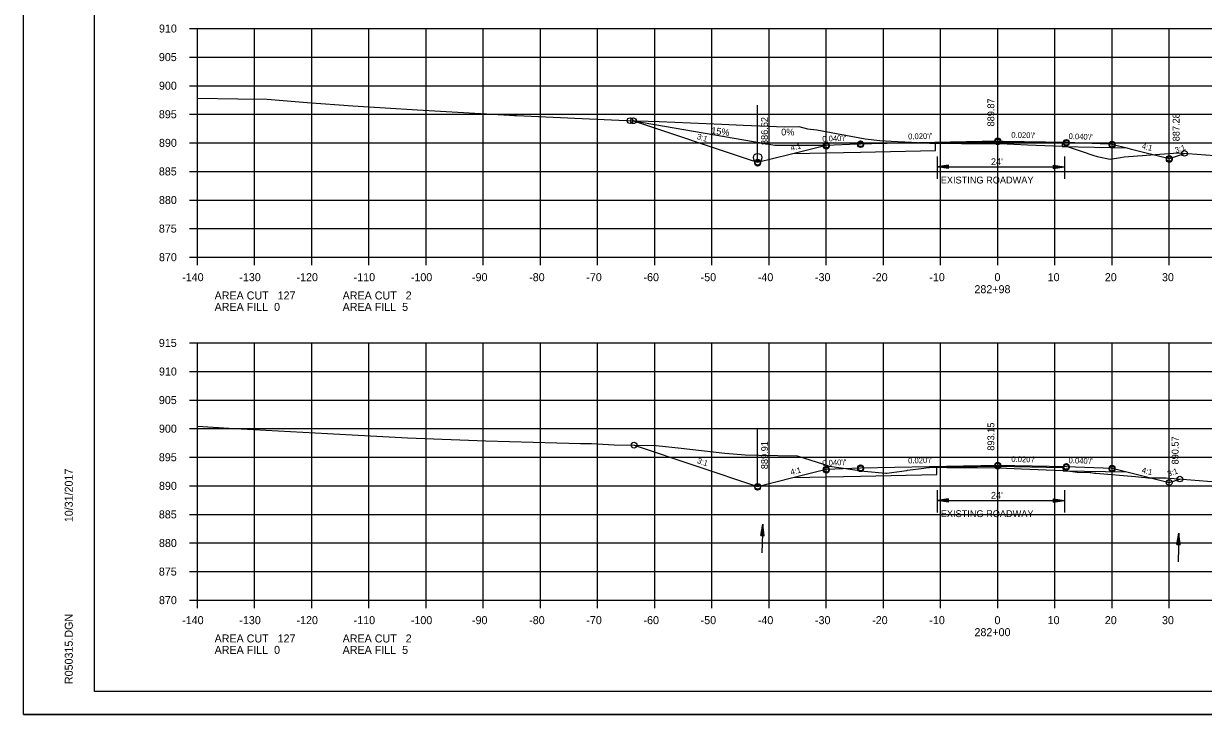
# Model space of a CAD drawing. Extents: x 1486524 to 1499135, y 326561 to 337924.
# Drawn here: x 1488812.5 to 1489018.9, y 331926 to 332046.8 of the extents above; entities that cross this region are included whole.
import ezdxf

# ---------------------------------------------------------------- set-up
doc = ezdxf.new("R2010")
doc.units = 0
for name, color, linetype in [('E_Const Align', 7, 'Continuous'), ('E_Const Align Station', 7, 'Continuous'), ('E_Ownership Information', 7, 'Continuous'), ('E_Property Line', 7, 'Continuous'), ('E_Proposed ROW and Easements', 7, 'Continuous'), ('E_Proposed ROW Fig Annot', 7, 'Continuous'), ('E_Quarter Calls', 7, 'Continuous'), ('E_Station Offset', 7, 'Continuous'), ('E_Survey Point', 7, 'Continuous'), ('E_Title Sheet', 7, 'Continuous'), ('E_Tract Number', 7, 'Continuous'), ('R_Water Annot', 7, 'Continuous'), ('R_Xsect Elev', 7, 'Continuous'), ('R_Xsect Slope', 7, 'Continuous')]:
    doc.layers.add(name, color=color, linetype=linetype)

msp = doc.modelspace()

# ---------------------------------------------------------------- linework, layer by layer
at = {"layer": 'E_Const Align'}
for p, q in [((1488841.49, 332045.94), (1488842.89, 332045.94)), ((1488842.89, 332005.94), (1488842.89, 332045.94)), ((1488841.49, 332040.94), (1488842.89, 332040.94)), ((1488841.49, 332035.94), (1488842.89, 332035.94)), ((1488841.49, 332030.94), (1488842.89, 332030.94)), ((1488841.49, 332025.94), (1488842.89, 332025.94)), ((1488841.49, 332020.94), (1488842.89, 332020.94)), ((1488841.49, 332015.94), (1488842.89, 332015.94)), ((1488841.49, 332010.94), (1488842.89, 332010.94)), ((1488841.49, 332005.94), (1488842.89, 332005.94)), ((1488842.89, 332005.94), (1489122.89, 332005.94)), ((1488842.89, 332004.54), (1488842.89, 332005.94)), ((1488852.89, 332004.54), (1488852.89, 332005.94)), ((1488862.89, 332004.54), (1488862.89, 332005.94)), ((1488872.89, 332004.54), (1488872.89, 332005.94)), ((1488882.89, 332004.54), (1488882.89, 332005.94)), ((1488892.89, 332004.54), (1488892.89, 332005.94)), ((1488902.89, 332004.54), (1488902.89, 332005.94)), ((1488912.89, 332004.54), (1488912.89, 332005.94)), ((1488922.89, 332004.54), (1488922.89, 332005.94)), ((1488932.89, 332004.54), (1488932.89, 332005.94)), ((1488942.89, 332004.54), (1488942.89, 332005.94)), ((1488952.89, 332004.54), (1488952.89, 332005.94)), ((1488962.89, 332004.54), (1488962.89, 332005.94)), ((1488972.89, 332004.54), (1488972.89, 332005.94)), ((1488982.89, 332004.54), (1488982.89, 332005.94)), ((1488992.89, 332004.54), (1488992.89, 332005.94)), ((1489002.89, 332004.54), (1489002.89, 332005.94)), ((1489012.89, 332004.54), (1489012.89, 332005.94)), ((1488841.49, 331990.94), (1488842.89, 331990.94)), ((1488842.89, 331945.94), (1488842.89, 331990.94)), ((1488841.49, 331985.94), (1488842.89, 331985.94)), ((1488841.49, 331980.94), (1488842.89, 331980.94)), ((1488841.49, 331975.94), (1488842.89, 331975.94)), ((1488841.49, 331970.94), (1488842.89, 331970.94)), ((1488841.49, 331965.94), (1488842.89, 331965.94)), ((1488841.49, 331960.94), (1488842.89, 331960.94)), ((1488841.49, 331955.94), (1488842.89, 331955.94)), ((1488841.49, 331950.94), (1488842.89, 331950.94)), ((1488841.49, 331945.94), (1488842.89, 331945.94)), ((1488842.89, 331945.94), (1489122.89, 331945.94)), ((1488842.89, 331944.54), (1488842.89, 331945.94)), ((1488852.89, 331944.54), (1488852.89, 331945.94)), ((1488862.89, 331944.54), (1488862.89, 331945.94)), ((1488872.89, 331944.54), (1488872.89, 331945.94)), ((1488882.89, 331944.54), (1488882.89, 331945.94)), ((1488892.89, 331944.54), (1488892.89, 331945.94)), ((1488902.89, 331944.54), (1488902.89, 331945.94)), ((1488912.89, 331944.54), (1488912.89, 331945.94)), ((1488922.89, 331944.54), (1488922.89, 331945.94)), ((1488932.89, 331944.54), (1488932.89, 331945.94)), ((1488942.89, 331944.54), (1488942.89, 331945.94)), ((1488952.89, 331944.54), (1488952.89, 331945.94)), ((1488962.89, 331944.54), (1488962.89, 331945.94)), ((1488972.89, 331944.54), (1488972.89, 331945.94)), ((1488982.89, 331944.54), (1488982.89, 331945.94)), ((1488992.89, 331944.54), (1488992.89, 331945.94)), ((1489002.89, 331944.54), (1489002.89, 331945.94)), ((1489012.89, 331944.54), (1489012.89, 331945.94))]:
    msp.add_line(p, q, dxfattribs=at)
at = {"layer": 'E_Ownership Information'}
for p, q in [((1488842.89, 332045.94), (1489122.89, 332045.94)), ((1488842.89, 332005.94), (1488842.89, 332045.94)), ((1488852.89, 332005.94), (1488852.89, 332045.94)), ((1488862.89, 332005.94), (1488862.89, 332045.94)), ((1488872.89, 332005.94), (1488872.89, 332045.94)), ((1488882.89, 332005.94), (1488882.89, 332045.94)), ((1488892.89, 332005.94), (1488892.89, 332045.94)), ((1488902.89, 332005.94), (1488902.89, 332045.94)), ((1488912.89, 332005.94), (1488912.89, 332045.94)), ((1488922.89, 332005.94), (1488922.89, 332045.94)), ((1488932.89, 332005.94), (1488932.89, 332045.94)), ((1488942.89, 332005.94), (1488942.89, 332045.94)), ((1488952.89, 332005.94), (1488952.89, 332045.94)), ((1488962.89, 332005.94), (1488962.89, 332045.94)), ((1488972.89, 332005.94), (1488972.89, 332045.94)), ((1488982.89, 332005.94), (1488982.89, 332045.94)), ((1488992.89, 332005.94), (1488992.89, 332045.94)), ((1489002.89, 332005.94), (1489002.89, 332045.94)), ((1489012.89, 332005.94), (1489012.89, 332045.94)), ((1488842.89, 332040.94), (1489122.89, 332040.94)), ((1488842.89, 332035.94), (1489122.89, 332035.94)), ((1488842.89, 332030.94), (1489122.89, 332030.94)), ((1488842.89, 332025.94), (1489122.89, 332025.94)), ((1488842.89, 332020.94), (1489122.89, 332020.94)), ((1488842.89, 332015.94), (1489122.89, 332015.94)), ((1488842.89, 332010.94), (1489122.89, 332010.94)), ((1488842.89, 332005.94), (1489122.89, 332005.94)), ((1488842.89, 331990.94), (1489122.89, 331990.94)), ((1488842.89, 331945.94), (1488842.89, 331990.94)), ((1488852.89, 331945.94), (1488852.89, 331990.94)), ((1488862.89, 331945.94), (1488862.89, 331990.94)), ((1488872.89, 331945.94), (1488872.89, 331990.94)), ((1488882.89, 331945.94), (1488882.89, 331990.94)), ((1488892.89, 331945.94), (1488892.89, 331990.94)), ((1488902.89, 331945.94), (1488902.89, 331990.94)), ((1488912.89, 331945.94), (1488912.89, 331990.94)), ((1488922.89, 331945.94), (1488922.89, 331990.94)), ((1488932.89, 331945.94), (1488932.89, 331990.94)), ((1488942.89, 331945.94), (1488942.89, 331990.94)), ((1488952.89, 331945.94), (1488952.89, 331990.94)), ((1488962.89, 331945.94), (1488962.89, 331990.94)), ((1488972.89, 331945.94), (1488972.89, 331990.94)), ((1488982.89, 331945.94), (1488982.89, 331990.94)), ((1488992.89, 331945.94), (1488992.89, 331990.94)), ((1489002.89, 331945.94), (1489002.89, 331990.94)), ((1489012.89, 331945.94), (1489012.89, 331990.94)), ((1488842.89, 331985.94), (1489122.89, 331985.94)), ((1488842.89, 331980.94), (1489122.89, 331980.94)), ((1488842.89, 331975.94), (1489122.89, 331975.94)), ((1488842.89, 331970.94), (1489122.89, 331970.94)), ((1488842.89, 331965.94), (1489122.89, 331965.94)), ((1488842.89, 331960.94), (1489122.89, 331960.94)), ((1488842.89, 331955.94), (1489122.89, 331955.94)), ((1488842.89, 331950.94), (1489122.89, 331950.94)), ((1488842.89, 331945.94), (1489122.89, 331945.94))]:
    msp.add_line(p, q, dxfattribs=at)
at = {"layer": 'E_Property Line'}
for p, q in [((1488824.89, 331929.94), (1488824.89, 332135.4)), ((1488824.89, 331929.94), (1488824.89, 331929.94)), ((1489141.07, 331929.94), (1488824.89, 331929.94))]:
    msp.add_line(p, q, dxfattribs=at)
at = {"layer": 'E_Proposed ROW and Easements'}
for p, q in [((1488972.3, 332023.55), (1488972.3, 332019.62)), ((1488974.3, 332022.04), (1488972.3, 332021.74)), ((1488974.3, 332021.99), (1488972.63, 332021.74)), ((1488974.3, 332021.93), (1488972.98, 332021.74)), ((1488974.3, 332021.88), (1488973.31, 332021.74)), ((1488974.3, 332021.44), (1488974.3, 332022.04)), ((1488992.58, 332022.04), (1488994.58, 332021.74)), ((1488992.58, 332022.04), (1488992.58, 332021.44)), ((1488992.58, 332021.99), (1488994.24, 332021.74)), ((1488992.58, 332021.94), (1488993.9, 332021.74)), ((1488992.58, 332021.89), (1488993.57, 332021.74)), ((1488994.58, 332023.55), (1488994.58, 332019.62)), ((1488974.3, 332021.44), (1488972.3, 332021.74)), ((1488974.3, 332021.49), (1488972.63, 332021.74)), ((1488974.3, 332021.54), (1488972.98, 332021.74)), ((1488974.3, 332021.59), (1488973.31, 332021.74)), ((1488974.3, 332021.83), (1488973.65, 332021.74)), ((1488974.3, 332021.64), (1488973.65, 332021.74)), ((1488974.3, 332021.78), (1488973.98, 332021.74)), ((1488974.3, 332021.69), (1488973.98, 332021.74)), ((1488992.58, 332021.84), (1488993.23, 332021.74)), ((1488992.58, 332021.79), (1488992.89, 332021.74)), ((1488992.58, 332021.44), (1488994.58, 332021.74)), ((1488992.58, 332021.64), (1488993.23, 332021.74)), ((1488992.58, 332021.54), (1488993.9, 332021.74)), ((1488992.58, 332021.49), (1488994.24, 332021.74)), ((1488992.58, 332021.59), (1488993.57, 332021.74)), ((1488992.58, 332021.69), (1488992.89, 332021.74)), ((1488972.3, 331965.19), (1488972.3, 331961.26)), ((1488994.58, 331965.19), (1488994.58, 331961.26)), ((1488974.3, 331963.67), (1488972.3, 331963.37)), ((1488974.3, 331963.07), (1488972.3, 331963.37)), ((1488974.3, 331963.62), (1488972.63, 331963.37)), ((1488974.3, 331963.12), (1488972.63, 331963.37)), ((1488974.3, 331963.57), (1488972.98, 331963.37)), ((1488974.3, 331963.18), (1488972.98, 331963.37)), ((1488974.3, 331963.52), (1488973.31, 331963.37)), ((1488974.3, 331963.23), (1488973.31, 331963.37)), ((1488974.3, 331963.47), (1488973.65, 331963.37)), ((1488974.3, 331963.28), (1488973.65, 331963.37)), ((1488974.3, 331963.42), (1488973.98, 331963.37)), ((1488974.3, 331963.33), (1488973.98, 331963.37)), ((1488974.3, 331963.07), (1488974.3, 331963.67)), ((1488992.58, 331963.68), (1488994.58, 331963.38)), ((1488992.58, 331963.68), (1488992.58, 331963.08)), ((1488992.58, 331963.63), (1488994.24, 331963.38)), ((1488992.58, 331963.58), (1488993.9, 331963.38)), ((1488992.58, 331963.53), (1488993.57, 331963.38)), ((1488992.58, 331963.48), (1488993.23, 331963.38)), ((1488992.58, 331963.43), (1488992.89, 331963.38)), ((1488992.58, 331963.08), (1488994.58, 331963.38)), ((1488992.58, 331963.28), (1488993.23, 331963.38)), ((1488992.58, 331963.18), (1488993.9, 331963.38)), ((1488992.58, 331963.13), (1488994.24, 331963.38)), ((1488992.58, 331963.23), (1488993.57, 331963.38)), ((1488992.58, 331963.33), (1488992.89, 331963.38))]:
    msp.add_line(p, q, dxfattribs=at)
at = {"layer": 'E_Proposed ROW Fig Annot'}
for p, q in [((1488972.3, 332021.74), (1488994.58, 332021.74)), ((1488972.3, 331963.37), (1488994.58, 331963.38)), ((1488941.42, 331957.23), (1488941.78, 331959.22)), ((1488941.42, 331957.23), (1488941.78, 331959.22)), ((1488941.47, 331957.23), (1488941.77, 331958.89)), ((1488941.47, 331957.23), (1488941.77, 331958.89)), ((1488941.52, 331957.23), (1488941.76, 331958.54)), ((1488941.52, 331957.23), (1488941.76, 331958.54)), ((1488941.57, 331957.23), (1488941.75, 331958.21)), ((1488941.57, 331957.23), (1488941.75, 331958.21)), ((1488941.86, 331957.22), (1488941.75, 331958.21)), ((1488941.86, 331957.22), (1488941.75, 331958.21)), ((1488941.91, 331957.21), (1488941.76, 331958.54)), ((1488941.91, 331957.21), (1488941.76, 331958.54)), ((1488941.97, 331957.21), (1488941.77, 331958.89)), ((1488941.97, 331957.21), (1488941.77, 331958.89)), ((1488942.02, 331957.21), (1488941.78, 331959.22)), ((1488942.02, 331957.21), (1488941.78, 331959.22)), ((1488941.42, 331957.23), (1488942.02, 331957.21)), ((1488941.42, 331957.23), (1488942.02, 331957.21)), ((1488941.62, 331957.22), (1488941.74, 331957.87)), ((1488941.62, 331957.22), (1488941.74, 331957.87)), ((1488941.67, 331957.22), (1488941.72, 331957.54)), ((1488941.67, 331957.22), (1488941.72, 331957.54)), ((1488941.76, 331957.22), (1488941.72, 331957.54)), ((1488941.76, 331957.22), (1488941.72, 331957.54)), ((1488941.81, 331957.22), (1488941.74, 331957.87)), ((1488941.81, 331957.22), (1488941.74, 331957.87)), ((1489014.22, 331955.66), (1489014.59, 331957.65)), ((1489014.22, 331955.66), (1489014.59, 331957.65)), ((1489014.27, 331955.66), (1489014.58, 331957.31)), ((1489014.27, 331955.66), (1489014.58, 331957.31)), ((1489014.32, 331955.66), (1489014.56, 331956.97)), ((1489014.32, 331955.66), (1489014.56, 331956.97)), ((1489014.37, 331955.65), (1489014.55, 331956.64)), ((1489014.37, 331955.65), (1489014.55, 331956.64)), ((1489014.43, 331955.65), (1489014.54, 331956.3)), ((1489014.43, 331955.65), (1489014.54, 331956.3)), ((1489014.48, 331955.65), (1489014.53, 331955.97)), ((1489014.48, 331955.65), (1489014.53, 331955.97)), ((1489014.57, 331955.65), (1489014.53, 331955.97)), ((1489014.57, 331955.65), (1489014.53, 331955.97)), ((1489014.62, 331955.65), (1489014.54, 331956.3)), ((1489014.62, 331955.65), (1489014.54, 331956.3)), ((1489014.67, 331955.64), (1489014.55, 331956.64)), ((1489014.67, 331955.64), (1489014.55, 331956.64)), ((1489014.72, 331955.64), (1489014.56, 331956.97)), ((1489014.72, 331955.64), (1489014.56, 331956.97)), ((1489014.77, 331955.64), (1489014.58, 331957.31)), ((1489014.77, 331955.64), (1489014.58, 331957.31)), ((1489014.82, 331955.64), (1489014.59, 331957.65)), ((1489014.82, 331955.64), (1489014.59, 331957.65)), ((1489014.22, 331955.66), (1489014.82, 331955.64)), ((1489014.22, 331955.66), (1489014.82, 331955.64))]:
    msp.add_line(p, q, dxfattribs=at)
at = {"layer": 'E_Quarter Calls'}
msp.add_line((1488812.48, 331925.96), (1489145.82, 331925.96), dxfattribs=at)
for points in [[(1488812.48, 332139.29), (1489145.82, 332139.29), (1489145.82, 331925.95), (1488812.48, 331925.95)], [(1489058.81, 332135.4), (1489058.81, 332125.52), (1489094.54, 332125.52), (1489094.54, 332122.6), (1489117.74, 332122.6), (1489117.74, 332098.26), (1489141.07, 332098.26), (1489141.07, 331929.94), (1488824.89, 331929.94), (1488824.89, 332135.4)]]:
    msp.add_lwpolyline(points, close=True, dxfattribs=at)
for centre in [(1488918.56, 332029.82), (1488919.15, 332029.8), (1488919.15, 332029.8), (1488952.89, 332025.55), (1488952.89, 332025.55), (1488958.89, 332025.79), (1488958.89, 332025.79), (1488958.89, 332025.62), (1488982.89, 332026.27), (1488982.89, 332026.27), (1488982.89, 332026.1), (1488994.89, 332026.03), (1488994.89, 332026.03), (1488994.89, 332025.86), (1489002.89, 332025.71), (1489002.89, 332025.71), (1489002.89, 332025.54), (1488952.89, 332025.38), (1489015.56, 332024.1), (1489015.56, 332024.1), (1488940.89, 332022.55), (1488940.89, 332022.55), (1488940.89, 332022.38), (1489012.89, 332023.21), (1489012.89, 332023.21), (1489012.89, 332023.04), (1488919.27, 331973.05), (1488919.27, 331973.05), (1488952.89, 331968.85), (1488952.89, 331968.85), (1488952.89, 331968.68), (1488958.89, 331969.09), (1488958.89, 331969.09), (1488958.89, 331968.92), (1488982.89, 331969.57), (1488982.89, 331969.57), (1488982.89, 331969.4), (1488994.89, 331969.33), (1488994.89, 331969.33), (1488994.89, 331969.16), (1489002.89, 331969.01), (1489002.89, 331969.01), (1489002.89, 331968.84), (1488940.89, 331965.85), (1488940.89, 331965.85), (1488940.89, 331965.68), (1489012.89, 331966.51), (1489012.89, 331966.51), (1489014.75, 331967.13), (1489014.75, 331967.13)]:
    msp.add_circle(centre, 0.5, dxfattribs=at)
at = {"layer": 'E_Station Offset'}
for p, q in [((1488919.15, 332029.8), (1488943.89, 332025.55)), ((1488943.89, 332025.55), (1488952.89, 332025.55))]:
    msp.add_line(p, q, dxfattribs=at)
msp.add_circle((1488940.89, 332023.35), 0.75, dxfattribs=at)
at = {"layer": 'E_Survey Point'}
for points in [[(1488947.06, 332024.1), (1488958.89, 332024.33), (1488972, 332024.6), (1488972, 332025.89), (1488982.89, 332026.11), (1488994.17, 332025.88), (1488994.18, 332025.3), (1489005.45, 332025.07)], [(1488947.06, 331967.39), (1488958.89, 331967.63), (1488972.23, 331967.9), (1488972.23, 331969.19), (1488982.89, 331969.4), (1488994.3, 331969.17), (1488994.31, 331968.59), (1489005.45, 331968.37)]]:
    msp.add_lwpolyline(points, dxfattribs=at)
at = {"layer": 'E_Title Sheet'}
for points in [[(1488919.15, 332029.8), (1488939.21, 332023.11), (1488940.89, 332022.55), (1488946.57, 332023.97), (1488947.06, 332024.1), (1488947.53, 332024.21), (1488952.89, 332025.55), (1488958.41, 332025.77), (1488958.89, 332025.79), (1488960.81, 332025.83), (1488982.89, 332026.27), (1488983.85, 332026.25), (1488994.89, 332026.03), (1489002.25, 332025.74), (1489002.89, 332025.71), (1489003.09, 332025.66), (1489005.45, 332025.07), (1489006.05, 332024.92), (1489012.89, 332023.21), (1489013.09, 332023.28), (1489015.56, 332024.1)], [(1488919.27, 331973.05), (1488940.89, 331965.85), (1488947.06, 331967.39), (1488952.89, 331968.85), (1488958.89, 331969.09), (1488982.89, 331969.57), (1488994.89, 331969.33), (1489002.89, 331969.01), (1489005.45, 331968.37), (1489012.89, 331966.51), (1489014.75, 331967.13)]]:
    msp.add_lwpolyline(points, dxfattribs=at)
at = {"layer": 'E_Tract Number'}
for points in [[(1488842.89, 332033.74), (1488849.97, 332033.65), (1488855.06, 332033.56), (1488862.1, 332033), (1488870.08, 332032.4), (1488881.41, 332031.72), (1488897.5, 332030.78), (1488898.34, 332030.73), (1488898.73, 332030.7), (1488917.87, 332029.85), (1488923.68, 332029.66), (1488934.61, 332029.23), (1488938.34, 332029.01), (1488945.66, 332028.77), (1488948.12, 332028.82), (1488949.58, 332028.4), (1488951.22, 332028.19), (1488959.7, 332026.62), (1488962.24, 332026.34), (1488964.23, 332026.24), (1488967.81, 332026.06), (1488971.02, 332025.88), (1488971.53, 332025.88), (1488972, 332025.88), (1488976.55, 332025.85), (1488983.31, 332025.8), (1488988.1, 332025.62), (1488994.17, 332025.38), (1488994.63, 332025.33), (1488995.01, 332025.28), (1488997.63, 332024.4), (1488999.5, 332023.77), (1489000.29, 332023.58), (1489002.53, 332023.08), (1489004.39, 332023.37), (1489005, 332023.47), (1489014.4, 332024.18), (1489014.45, 332024.18), (1489014.55, 332024.18), (1489033.46, 332022.79)], [(1488842.89, 331976.36), (1488848.37, 331976.05), (1488865.65, 331975.09), (1488879.61, 331974.31), (1488893.33, 331973.83), (1488909.87, 331973.37), (1488911.81, 331973.33), (1488915.79, 331973.13), (1488919.33, 331973.05), (1488923.13, 331972.98), (1488927.48, 331972.5), (1488935.16, 331971.68), (1488937.3, 331971.49), (1488938.71, 331971.35), (1488941.1, 331971.31), (1488947.82, 331971.2), (1488952.4, 331969.73), (1488953.41, 331969.4), (1488953.86, 331969.34), (1488959.1, 331968.59), (1488959.5, 331968.53), (1488963.31, 331968.16), (1488963.46, 331968.15), (1488967, 331968.65), (1488967.08, 331968.66), (1488969.96, 331969.04), (1488970.72, 331969.16), (1488970.95, 331969.16), (1488972.23, 331969.18), (1488973.98, 331969.17), (1488983.16, 331969.08), (1488987.06, 331968.92), (1488994.3, 331968.61), (1488994.82, 331968.58), (1488995.1, 331968.56), (1488996.81, 331968.35), (1488996.84, 331968.35), (1488999.03, 331968.27), (1488999.18, 331968.29), (1488999.81, 331968.15), (1489000.04, 331968.16), (1489006.98, 331967.6), (1489008.06, 331967.47), (1489008.71, 331967.39), (1489009.17, 331967.34), (1489012.27, 331967.31), (1489021.05, 331966.66)]]:
    msp.add_lwpolyline(points, dxfattribs=at)
at = {"layer": 'R_Water Annot'}
for p, q in [((1488941.78, 331959.22), (1488941.62, 331954.22)), ((1489014.59, 331957.65), (1489014.43, 331952.65))]:
    msp.add_line(p, q, dxfattribs=at)
at = {"layer": 'R_Xsect Elev'}
for p, q in [((1488982.89, 332025.81), (1488982.89, 332035.81)), ((1488940.89, 332022.55), (1488940.89, 332032.55)), ((1489012.89, 332023.21), (1489012.89, 332033.21)), ((1488982.89, 331969.09), (1488982.89, 331979.09)), ((1489012.89, 331966.51), (1489012.89, 331976.51)), ((1488940.89, 331965.85), (1488940.89, 331975.85))]:
    msp.add_line(p, q, dxfattribs=at)

# ---------------------------------------------------------------- texts
at = {"layer": 'E_Const Align Station'}
for s, p in [('910', (1488836.16, 332045.24)), ('905', (1488836.14, 332040.24)), ('900', (1488836.16, 332035.24)), ('895', (1488836.14, 332030.24)), ('890', (1488836.16, 332025.24)), ('885', (1488836.14, 332020.24)), ('880', (1488836.16, 332015.24)), ('875', (1488836.14, 332010.24)), ('870', (1488836.16, 332005.24)), ('-140', (1488840.22, 332001.74)), ('-130', (1488850.22, 332001.74)), ('-120', (1488860.22, 332001.74)), ('-110', (1488870.22, 332001.74)), ('-100', (1488880.22, 332001.74)), ('-90', (1488890.92, 332001.74)), ('-80', (1488900.92, 332001.74)), ('-70', (1488910.92, 332001.74)), ('-60', (1488920.92, 332001.74)), ('-50', (1488930.92, 332001.74)), ('-40', (1488940.92, 332001.74)), ('-30', (1488950.92, 332001.74)), ('-20', (1488960.92, 332001.74)), ('-10', (1488970.92, 332001.74)), ('0', (1488982.32, 332001.74)), ('10', (1488991.62, 332001.74)), ('20', (1489001.62, 332001.74)), ('30', (1489011.62, 332001.74)), ('AREA CUT   127', (1488845.89, 331998.54)), ('AREA CUT   2', (1488868.29, 331998.54)), ('282+98', (1488978.81, 331999.64)), ('AREA FILL  0', (1488845.89, 331996.54)), ('AREA FILL  5', (1488868.29, 331996.54)), ('915', (1488836.14, 331990.24)), ('910', (1488836.16, 331985.24)), ('905', (1488836.14, 331980.24)), ('900', (1488836.16, 331975.24)), ('895', (1488836.14, 331970.24)), ('890', (1488836.16, 331965.24)), ('885', (1488836.14, 331960.24)), ('880', (1488836.16, 331955.24)), ('875', (1488836.14, 331950.24)), ('870', (1488836.16, 331945.24)), ('-140', (1488840.22, 331941.74)), ('-130', (1488850.22, 331941.74)), ('-120', (1488860.22, 331941.74)), ('-110', (1488870.22, 331941.74)), ('-100', (1488880.22, 331941.74)), ('-90', (1488890.92, 331941.74)), ('-80', (1488900.92, 331941.74)), ('-70', (1488910.92, 331941.74)), ('-60', (1488920.92, 331941.74)), ('-50', (1488930.92, 331941.74)), ('-40', (1488940.92, 331941.74)), ('-30', (1488950.92, 331941.74)), ('-20', (1488960.92, 331941.74)), ('-10', (1488970.92, 331941.74)), ('0', (1488982.32, 331941.74)), ('10', (1488991.62, 331941.74)), ('20', (1489001.62, 331941.74)), ('30', (1489011.62, 331941.74)), ('AREA CUT   127', (1488845.89, 331938.54)), ('AREA CUT   2', (1488868.29, 331938.54)), ('282+00', (1488978.82, 331939.64)), ('AREA FILL  0', (1488845.89, 331936.54)), ('AREA FILL  5', (1488868.29, 331936.54))]:
    msp.add_text(s, height=1.4, dxfattribs=at).set_placement(p)
at = {"layer": 'E_Property Line'}
for s, p in [('10/31/2017', (1488821.08, 331959.58)), ('R050315.DGN', (1488821.08, 331931.26))]:
    msp.add_text(s, height=1.4, rotation=90, dxfattribs=at).set_placement(p)
at = {"layer": 'E_Proposed ROW Fig Annot'}
for s, p in [("24'", (1488981.69, 332022.04)), ('EXISTING ROADWAY', (1488972.92, 332018.83)), ("24'", (1488981.69, 331963.68)), ('EXISTING ROADWAY', (1488972.92, 331960.47))]:
    msp.add_text(s, height=1.2, dxfattribs=at).set_placement(p)
at = {"layer": 'E_Station Offset'}
msp.add_text('15%', height=1.2, rotation=352.59, dxfattribs=at).set_placement((1488932.71, 332027.53))
msp.add_text('0%', height=1.2, dxfattribs=at).set_placement((1488945, 332027.23))
at = {"layer": 'R_Xsect Elev'}
for s, p in [('889.87', (1488982.29, 332028.81)), ('886.62', (1488942.69, 332025.55)), ('887.28', (1489014.69, 332026.21)), ('893.15', (1488982.29, 331972.09)), ('890.57', (1489014.52, 331969.68)), ('889.91', (1488942.69, 331968.85))]:
    msp.add_text(s, height=1.2, rotation=90, dxfattribs=at).set_placement(p)
at = {"layer": 'R_Xsect Slope'}
for s, rotation, p in [('3:1', 341.5651, (1488930.17, 332026.65)), ("0.040'/'", 2.2906, (1488952.21, 332026.13)), ("0.020'/'", 1.1458, (1488967.22, 332026.56)), ("0.020'/'", 358.8542, (1488985.25, 332026.83)), ("0.040'/'", 357.7094, (1488995.26, 332026.62)), ('4:1', 14.0362, (1488946.76, 332024.54)), ('4:1', 345.9638, (1489008.01, 332024.95)), ('3:1', 18.4349, (1489014.07, 332024.13)), ('3:1', 341.5651, (1488930.23, 331969.93)), ("0.040'/'", 2.2906, (1488952.21, 331969.42)), ("0.020'/'", 1.1458, (1488967.22, 331969.85)), ("0.020'/'", 358.8542, (1488985.25, 331970.12)), ("0.040'/'", 357.7094, (1488995.26, 331969.91)), ('4:1', 14.0362, (1488946.76, 331967.83)), ('4:1', 345.9638, (1489008.01, 331968.24)), ('3:1', 18.4349, (1489012.74, 331967.54))]:
    msp.add_text(s, height=1, rotation=rotation, dxfattribs=at).set_placement(p)

doc.saveas('drawing.dxf')
